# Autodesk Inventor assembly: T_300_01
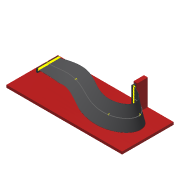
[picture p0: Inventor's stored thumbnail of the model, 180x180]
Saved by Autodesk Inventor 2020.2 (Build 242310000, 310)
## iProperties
Created: 2014-09
Part Number: T_300_01
Document SubType Name: Assembly
Designer: F.Stasiak
Catalog Web Link: www.expertbooks.pl
Manager: www.cadconsulting.pl
Company: Fabian Stasiak CAD Consulting
Author: F.Stasiak
Subject: Zbiór ćwiczeń. Autodesk Inventor 2020. Kurs Professional
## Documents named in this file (4)
- C:\2020_Kurs_Professional\R2 Wiązki\T_300_01.iam
- C:\2020_Kurs_Professional\R2 Wiązki\Komponenty\Konstrukcja_W3.ipt
- C:\2020_Kurs_Professional\Zasoby\ContentCenter\pl-PL\Ribbon Cable Connector\Ribbon Cable Connector-13.ipt
- C:\2020_Kurs_Professional\R2 Wiązki\T_300_01\AIP\przewody i wiązki przewodów\T_300_01.Wiązka przewodów1.iam
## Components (4 placed, 3 different names)
1. Konstrukcja_W3:1 — Zestawiający:1, Równoległy:1, Zestawiający:2, Równoległy:3, Równoległy:5, Równoległy:6
2. Złącze kabla taśmowego Ribbon Cable Connector-13:1 — Zestawiający:1, Równoległy:1, Równoległy:5
3. Złącze kabla taśmowego Ribbon Cable Connector-13:2 — Zestawiający:2, Równoległy:3, Równoległy:6
4. Wiązka przewodów1 [sub-assembly]
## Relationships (6: Flush 4, Mate 2)
- Zestawiający:1 [Mate]: Konstrukcja_W3:1 ↔ Złącze kabla taśmowego Ribbon Cable Connector-13:1
- Równoległy:1 [Flush]: Konstrukcja_W3:1 ↔ Złącze kabla taśmowego Ribbon Cable Connector-13:1
- Zestawiający:2 [Mate]: Konstrukcja_W3:1 ↔ Złącze kabla taśmowego Ribbon Cable Connector-13:2
- Równoległy:3 [Flush]: Konstrukcja_W3:1 ↔ Złącze kabla taśmowego Ribbon Cable Connector-13:2
- Równoległy:5 [Flush]: Konstrukcja_W3:1 ↔ Złącze kabla taśmowego Ribbon Cable Connector-13:1
- Równoległy:6 [Flush]: Konstrukcja_W3:1 ↔ Złącze kabla taśmowego Ribbon Cable Connector-13:2
